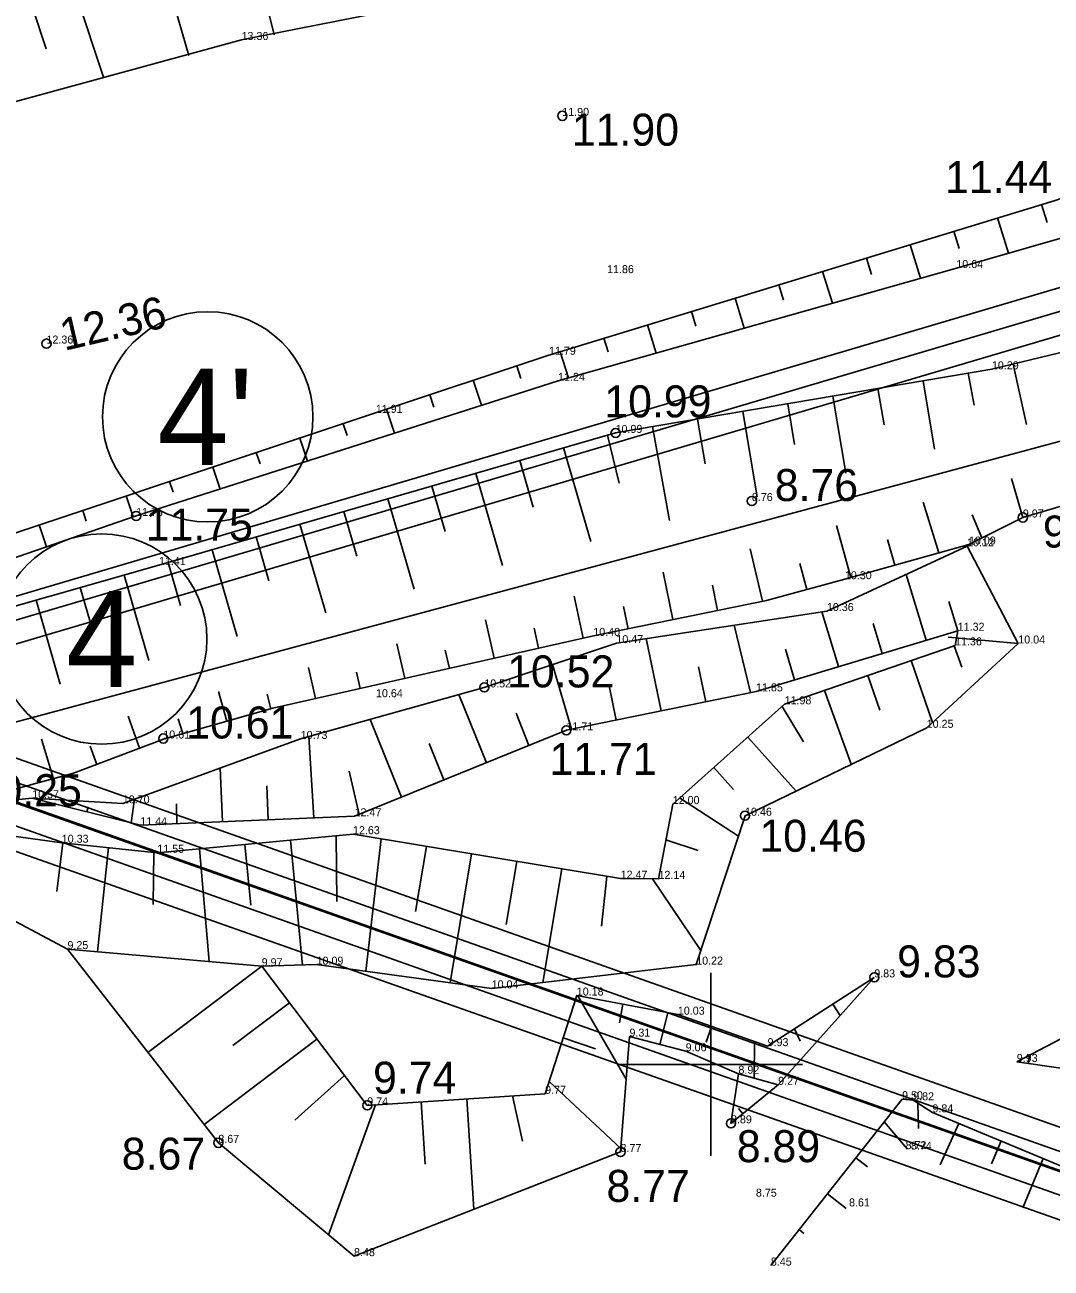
# Model space of a CAD drawing. Extents: x 433497 to 434382, y 6534486 to 6534993.
# Drawn here: x 433970 to 434014.9, y 6534891.1 to 6534945.5 of the extents above; entities that cross this region are included whole.
import ezdxf

# ---------------------------------------------------------------- set-up
doc = ezdxf.new("R2010")
doc.units = 0
for name, color, linetype in [('Default', 7, 'Continuous'), ('kataster', 7, 'Continuous'), ('KORGUS-EH2000', 7, 'Continuous'), ('MOOTKORG-EH2000', 7, 'Continuous'), ('PIIR', 7, 'Continuous'), ('RELJEEF', 7, 'Continuous'), ('VEEKOGU', 7, 'Continuous'), ('VORK', 7, 'Continuous')]:
    doc.layers.add(name, color=color, linetype=linetype)

msp = doc.modelspace()

# ---------------------------------------------------------------- linework, layer by layer
at = {"layer": 'Default'}
msp.add_lwpolyline([(433617.12, 6534791.025), (433632.75, 6534606.045), (434137.38, 6534796.515), (434127.69, 6534855.6), (433968.21, 6534911.925), (433942.38, 6534904.035), (433920.99, 6534907.275)], close=True, dxfattribs=at)
msp.add_lwpolyline([(433617.12, 6534791.025), (433632.75, 6534606.045), (434137.38, 6534796.515), (434127.69, 6534855.6), (433968.21, 6534911.925), (433942.38, 6534904.035), (433920.99, 6534907.275)], close=True, dxfattribs=at)
msp.add_lwpolyline([(433617.12, 6534791.025), (433632.75, 6534606.045), (434137.38, 6534796.515), (434127.69, 6534855.6), (433968.21, 6534911.925), (433942.38, 6534904.035), (433920.99, 6534907.275)], close=True, dxfattribs=at)
at = {"layer": 'kataster'}
msp.add_lwpolyline([(433617.102, 6534791.002), (433632.769, 6534606.029), (434137.446, 6534796.469), (434127.827, 6534855.589), (433950.026, 6534918.39)], close=True, dxfattribs=at)
at = {"layer": 'KORGUS-EH2000'}
for centre in [(433993.5, 6534941.49), (433970.95, 6534931.53), (433995.831, 6534927.622), (434001.79, 6534924.641), (433974.871, 6534923.99), (434013.638, 6534923.923), (433990.092, 6534916.489), (433976.058, 6534914.254), (433993.682, 6534914.612), (434001.493, 6534910.875), (434007.141, 6534903.804), (433984.974, 6534898.207), (434000.877, 6534897.42), (433978.465, 6534896.567), (433996.048, 6534896.167)]:
    msp.add_circle(centre, 0.2, dxfattribs=at)
at = {"layer": 'PIIR'}
for points in [[(433967.603, 6534912.278), (433955.91, 6534916.425), (434046.45, 6534943.215), (434054.366, 6534945.47)], [(433967.938, 6534913.221), (433959.144, 6534916.339), (434046.729, 6534942.255), (434054.64, 6534944.509)], [(433968.272, 6534914.163), (433962.378, 6534916.253), (434047.008, 6534941.294), (434054.914, 6534943.547)], [(434138.342, 6534801.592), (434129.36, 6534856.88), (433968.248, 6534913.871)], [(433632.021, 6534604.835), (434138.248, 6534795.936), (434128.468, 6534856.135), (433968.226, 6534912.818), (433942.33, 6534904.85), (433920.952, 6534908.165), (433616.327, 6534791.524), (433632.021, 6534604.835)], [(433632.732, 6534605.959), (434137.353, 6534796.454), (434127.754, 6534855.539), (433968.208, 6534911.976), (433942.39, 6534904.031), (433921.04, 6534907.341), (433617.174, 6534790.992), (433632.732, 6534605.959)]]:
    msp.add_lwpolyline(points, dxfattribs=at)
for points in [[(433618.234, 6534790.327), (433921.149, 6534906.313), (433942.464, 6534903.008), (433968.187, 6534910.923), (434126.862, 6534854.794), (434136.235, 6534797.101), (433633.617, 6534607.362)], [(433619.24, 6534789.695), (433634.52, 6534608.851), (434135.141, 6534797.808), (434125.908, 6534854.108), (433968.165, 6534909.82), (433942.53, 6534901.99), (433921.212, 6534905.219)], [(433619.24, 6534789.695), (433634.52, 6534608.851), (434135.141, 6534797.808), (434125.908, 6534854.108), (433968.165, 6534909.82), (433942.53, 6534901.99), (433921.212, 6534905.219)]]:
    msp.add_lwpolyline(points, close=True, dxfattribs=at)
for centre in [(433977.998, 6534928.325), (433973.364, 6534918.605)]:
    msp.add_circle(centre, 4.6, dxfattribs=at)
at = {"layer": 'RELJEEF'}
for p, q in [((433979.915, 6534949.055), (433980.899, 6534945.037)), ((433976.03, 6534948.103), (433977.167, 6534944.132)), ((433972.231, 6534946.852), (433973.457, 6534943.139)), ((433970.941, 6534944.427), (433970.332, 6534946.224)), ((434014.694, 6534936.827), (434014.446, 6534937.611)), ((434012.533, 6534937.026), (434013.004, 6534935.486)), ((434010.851, 6534935.687), (434010.621, 6534936.441)), ((434008.709, 6534935.855), (434009.158, 6534934.388)), ((434007.014, 6534934.556), (434006.796, 6534935.27)), ((434004.884, 6534934.685), (434005.308, 6534933.297)), ((434003.177, 6534933.426), (434002.971, 6534934.1)), ((434001.059, 6534933.515), (434001.459, 6534932.207)), ((433999.34, 6534932.295), (433999.146, 6534932.93)), ((433997.234, 6534932.344), (433997.609, 6534931.116)), ((433995.503, 6534931.165), (433995.321, 6534931.759)), ((433993.409, 6534931.174), (433993.77, 6534930.028)), ((433991.691, 6534929.996), (433991.507, 6534930.555)), ((434011.507, 6534928.837), (434011.248, 6534930.228)), ((434013.207, 6534930.626), (434013.794, 6534927.992)), ((433989.61, 6534929.922), (433989.974, 6534928.829)), ((434009.276, 6534929.894), (434009.78, 6534926.912)), ((433987.891, 6534928.754), (433987.712, 6534929.29)), ((434005.332, 6534929.228), (434005.9, 6534925.868)), ((434007.572, 6534927.976), (434007.304, 6534929.561)), ((433985.815, 6534928.658), (433986.165, 6534927.608)), ((434001.388, 6534928.561), (434002.02, 6534924.824)), ((434003.66, 6534927.12), (434003.36, 6534928.895)), ((433984.089, 6534927.512), (433983.918, 6534928.025)), ((433999.748, 6534926.265), (433999.416, 6534928.228)), ((433995.983, 6534925.428), (433995.481, 6534927.521)), ((433997.444, 6534927.895), (433998.182, 6534923.792)), ((433982.02, 6534927.393), (433982.355, 6534926.388)), ((433993.56, 6534926.964), (433994.747, 6534922.867)), ((433980.287, 6534926.269), (433980.123, 6534926.76)), ((433992.227, 6534924.378), (433991.639, 6534926.408)), ((433978.225, 6534926.128), (433978.546, 6534925.167)), ((433989.718, 6534925.852), (433990.883, 6534921.828)), ((433976.484, 6534925.026), (433976.328, 6534925.495)), ((433988.374, 6534923.302), (433987.797, 6534925.296)), ((434013.638, 6534923.923), (434013.134, 6534925.628)), ((433974.431, 6534924.863), (433974.737, 6534923.944)), ((433985.876, 6534924.739), (433987.02, 6534920.789)), ((433972.69, 6534923.761), (433972.533, 6534924.23)), ((433984.522, 6534922.226), (433983.955, 6534924.183)), ((434009.968, 6534922.374), (434009.273, 6534924.589)), ((433982.034, 6534923.627), (433983.157, 6534919.749)), ((434011.422, 6534924.04), (434011.85, 6534923.027)), ((433970.636, 6534923.598), (433970.955, 6534922.641)), ((434006.117, 6534921.292), (434005.488, 6534923.571)), ((433980.669, 6534921.15), (433980.113, 6534923.07)), ((434002.253, 6534920.26), (434001.715, 6534922.556)), ((434007.726, 6534922.96), (434008.042, 6534921.833)), ((433978.192, 6534922.514), (433979.293, 6534918.71)), ((433976.814, 6534920.073), (433976.271, 6534921.958)), ((433998.335, 6534919.455), (433997.908, 6534921.532)), ((434003.881, 6534921.913), (434004.186, 6534920.769)), ((433974.348, 6534921.406), (433975.419, 6534917.668)), ((434000.068, 6534920.955), (434000.294, 6534919.857)), ((434009.403, 6534918.551), (434008.536, 6534921.431)), ((433972.956, 6534919.002), (433972.425, 6534920.856)), ((433994.418, 6534918.641), (433994.017, 6534920.485)), ((433970.503, 6534920.306), (433971.555, 6534916.628)), ((433996.172, 6534920.031), (433996.376, 6534919.052)), ((434010.79, 6534918.968), (434010.407, 6534920.241)), ((433990.516, 6534917.761), (433990.137, 6534919.441)), ((434005.573, 6534917.398), (434004.85, 6534919.798)), ((434007.095, 6534919.279), (434007.488, 6534917.974)), ((433992.269, 6534919.081), (433992.467, 6534918.201)), ((434001.737, 6534916.266), (434001.01, 6534919.212)), ((434010.674, 6534918.326), (434010.79, 6534918.968)), ((433986.614, 6534916.881), (433986.272, 6534918.401)), ((433997.819, 6534915.462), (433997.169, 6534918.626)), ((434010.374, 6534918.689), (434013.438, 6534918.41)), ((434010.964, 6534917.373), (434010.639, 6534918.314)), ((433988.385, 6534918.121), (433988.565, 6534917.321)), ((434003.263, 6534918.158), (434003.658, 6534916.821)), ((434008.749, 6534917.661), (434009.684, 6534914.953)), ((433982.712, 6534916.001), (433982.404, 6534917.361)), ((433984.501, 6534917.161), (433984.663, 6534916.441)), ((433993.901, 6534914.657), (433993.074, 6534917.49)), ((433999.463, 6534917.396), (433999.778, 6534915.864)), ((433995.536, 6534916.634), (433995.86, 6534915.059)), ((434007.381, 6534915.495), (434006.858, 6534917.008)), ((433978.838, 6534915.012), (433978.473, 6534916.303)), ((433980.6, 6534916.194), (433980.762, 6534915.557)), ((433990.182, 6534913.192), (433988.972, 6534916.175)), ((434004.968, 6534916.355), (434006.137, 6534913.125)), ((434004.044, 6534914.107), (434003.108, 6534915.651)), ((433975.02, 6534913.83), (433974.515, 6534915.238)), ((433976.711, 6534915.121), (433976.914, 6534914.467)), ((433986.476, 6534911.687), (433985.096, 6534915.087)), ((433991.479, 6534915.356), (433992.036, 6534913.944)), ((433971.253, 6534912.495), (433970.736, 6534914.221)), ((433972.856, 6534913.916), (433973.15, 6534913.119)), ((433982.64, 6534910.778), (433982.426, 6534914.338)), ((433987.682, 6534914.035), (433988.329, 6534912.439)), ((434001.615, 6534914.319), (434003.724, 6534911.956)), ((433978.644, 6534910.611), (433978.546, 6534912.96)), ((433984.177, 6534912.82), (433984.623, 6534910.935)), ((434000.988, 6534912.018), (434000.123, 6534912.987)), ((433980.58, 6534912.185), (433980.642, 6534910.695)), ((433998.631, 6534911.656), (434001.199, 6534909.979)), ((433970.778, 6534911.527), (433970.788, 6534911.614)), ((433972.775, 6534911.271), (433972.719, 6534911.043)), ((433974.659, 6534910.559), (433974.795, 6534911.599)), ((433976.635, 6534911.395), (433976.646, 6534910.528)), ((433971.409, 6534907.556), (433971.666, 6534909.689)), ((433973.655, 6534909.48), (433973.178, 6534904.926)), ((433979.879, 6534906.966), (433979.627, 6534909.62)), ((433981.618, 6534909.809), (433982.137, 6534904.343)), ((433983.647, 6534907.117), (433983.609, 6534909.998)), ((433985.588, 6534909.863), (433984.911, 6534904.07)), ((433987.088, 6534906.687), (433987.561, 6534909.535)), ((433999.435, 6534909.348), (433998.033, 6534909.818)), ((433975.616, 6534906.993), (433975.645, 6534909.272)), ((433977.635, 6534909.431), (433978.067, 6534904.494)), ((433989.534, 6534909.207), (433988.597, 6534903.571)), ((433991.047, 6534906.112), (433991.507, 6534908.879)), ((433993.48, 6534908.551), (433992.654, 6534903.585)), ((433995.212, 6534906.039), (433995.453, 6534908.223)), ((433997.445, 6534908.115), (433999.556, 6534904.974)), ((433980.359, 6534904.292), (433975.387, 6534900.521)), ((434007.024, 6534903.703), (434007.013, 6534903.721)), ((434007.141, 6534903.804), (434007.141, 6534903.804)), ((433994.187, 6534903.001), (433996.294, 6534899.345)), ((433979.092, 6534900.821), (433981.568, 6534902.698)), ((433995.997, 6534901.814), (433996.152, 6534902.629)), ((434005.332, 6534902.637), (434005.653, 6534902.14)), ((433998.117, 6534902.257), (433997.768, 6534900.867)), ((433999.793, 6534900.973), (434000.021, 6534901.659)), ((434003.906, 6534901.013), (434003.651, 6534901.553)), ((433982.776, 6534901.105), (433977.844, 6534897.364)), ((433994.949, 6534900.682), (433993.539, 6534901.157)), ((434001.908, 6534900.996), (434001.885, 6534899.399)), ((434013.882, 6534900.032), (434013.934, 6534900.4)), ((434013.372, 6534900.105), (434013.372, 6534900.105)), ((433981.803, 6534897.557), (433983.985, 6534899.511)), ((433992.926, 6534899.253), (433996.06, 6534896.318)), ((433991.767, 6534896.643), (433991.324, 6534898.619)), ((434002.939, 6534899.105), (434000.877, 6534897.42)), ((433985.336, 6534898.231), (433983.28, 6534892.544)), ((433987.509, 6534895.629), (433987.332, 6534898.36)), ((433989.328, 6534898.49), (433989.641, 6534893.662)), ((434001.2, 6534898.072), (434001.39, 6534897.839)), ((434009.076, 6534897.191), (434009.05, 6534898.298)), ((434000.877, 6534897.42), (434000.877, 6534897.42)), ((434007.573, 6534897.482), (434008.59, 6534896.284)), ((434010.839, 6534897.418), (434010.018, 6534895.609)), ((434012.27, 6534895.652), (434012.685, 6534896.648)), ((434006.842, 6534895.512), (434006.335, 6534895.911)), ((434014.531, 6534895.879), (434013.635, 6534893.73)), ((434005.097, 6534894.341), (434005.918, 6534893.693)), ((434004.064, 6534892.608), (434003.859, 6534892.77)), ((434002.621, 6534891.199), (434002.621, 6534891.199))]:
    msp.add_line(p, q, dxfattribs=at)
for points in [[(433954.03, 6534938.79), (433965.22, 6534940.93), (433979.48, 6534944.81), (434000.61, 6534948.99), (434020.069, 6534953.305), (434024.103, 6534954.537)], [(433936.113, 6534913.569), (433948.309, 6534917.667), (433964.567, 6534921.575), (433985.421, 6534928.526), (433992.869, 6534931.009), (434015.046, 6534937.794), (434037.058, 6534945.242), (434046.777, 6534948.114)], [(434057.361, 6534943.115), (434035.636, 6534936.058), (434012.285, 6534930.403), (433995.831, 6534927.622), (433975.867, 6534921.841), (433966.352, 6534919.118), (433953.883, 6534915.376), (433941.75, 6534912.389)], [(434034.795, 6534941.742), (434010.729, 6534934.833), (433993.318, 6534929.9), (433974.871, 6534923.99), (433964.528, 6534920.427), (433953.287, 6534916.572), (433941.75, 6534912.389)], [(434013.638, 6534923.923), (434032.965, 6534929.639), (434058.719, 6534936.872), (434065.592, 6534938.633), (434071.86, 6534940.43)], [(434013.638, 6534923.923), (434011.282, 6534922.743), (434005.856, 6534921.218), (434002.425, 6534920.296), (433994.862, 6534918.741), (433980.849, 6534915.581), (433976.065, 6534914.227), (433972.133, 6534912.733), (433966.809, 6534911.293), (433961.061, 6534910.056), (433948.062, 6534907.022), (433934.725, 6534902.808)], [(434013.438, 6534918.41), (434011.201, 6534922.662), (434005.07, 6534919.831), (433995.866, 6534918.427), (433990.092, 6534916.489), (433982.062, 6534914.236), (433974.288, 6534911.415), (433970.327, 6534911.64)], [(433966.809, 6534911.293), (433970.327, 6534911.64), (433975.054, 6534910.461), (433984.421, 6534910.853), (433993.682, 6534914.612), (434001.975, 6534916.315), (434010.79, 6534918.968)], [(433934.885, 6534901.473), (433948.355, 6534905.609), (433960.823, 6534908.761), (433967.491, 6534910.261), (433971.618, 6534909.694), (433975.796, 6534909.256), (433984.352, 6534910.069), (433996.051, 6534908.124), (433997.709, 6534908.113), (433998.331, 6534911.388), (434003.22, 6534915.751), (434010.674, 6534918.326)], [(433935.534, 6534899.657), (433948.664, 6534904.432), (433960.648, 6534906.657), (433966.716, 6534907.784), (433971.868, 6534905.042), (433980.359, 6534904.292), (433982.759, 6534904.361), (433990.414, 6534903.325), (433999.356, 6534904.364), (434001.493, 6534910.875), (434009.433, 6534914.722), (434013.438, 6534918.41)], [(434072.341, 6534918.619), (434057.705, 6534915.179), (434049.799, 6534913.566), (434039.083, 6534902.565), (434026.545, 6534900.533), (434022.06, 6534899.903), (434019.453, 6534899.237), (434013.372, 6534900.105)], [(434013.372, 6534900.105), (434019.896, 6534903.523), (434025.539, 6534902.847), (434027.394, 6534902.614), (434034.232, 6534903.967), (434040.473, 6534912.406), (434048.11, 6534914.669), (434057.958, 6534916.499), (434064.857, 6534918.437), (434072.341, 6534918.619)], [(433971.868, 6534905.042), (433978.465, 6534896.567), (433984.397, 6534891.611), (433996.048, 6534896.167), (433996.438, 6534901.214), (433998.896, 6534900.572), (434001.203, 6534899.589), (434002.939, 6534899.105), (434007.141, 6534903.804)], [(433980.359, 6534904.292), (433984.974, 6534898.207), (433992.752, 6534898.712), (433994.135, 6534903.011), (433998.554, 6534902.174), (434002.477, 6534900.796), (434007.141, 6534903.804)], [(434000.877, 6534897.42), (434001.203, 6534899.589)], [(434002.621, 6534891.199), (434008.357, 6534898.477), (434008.844, 6534898.428), (434009.684, 6534897.899), (434020.673, 6534893.319), (434025.184, 6534891.367), (434026.4, 6534888.82), (434028.53, 6534881.31), (434029.71, 6534869.667), (434036.879, 6534848.772), (434040.385, 6534828.949), (434036.914, 6534815.456), (434039.48, 6534802.82), (434040.271, 6534794.377), (434046.22, 6534786.31), (434052.87, 6534782.4), (434066.43, 6534782.05), (434080.61, 6534786.771), (434096.029, 6534790.927), (434100.314, 6534792.082), (434103.079, 6534792.827), (434103.7, 6534784.75)]]:
    msp.add_lwpolyline(points, dxfattribs=at)
at = {"layer": 'VEEKOGU'}
msp.add_lwpolyline([(433938.353, 6534906.567), (434032.024, 6534931.768), (434057.768, 6534939.003)], dxfattribs=at)
at = {"layer": 'VORK'}
for p, q in [((434000, 6534904), (434000, 6534896)), ((433996, 6534900), (434004, 6534900))]:
    msp.add_line(p, q, dxfattribs=at)

# ---------------------------------------------------------------- texts
at = {"layer": 'KORGUS-EH2000'}
for s, p in [('11.90', (433993.92, 6534940.185)), ('11.44', (434010.236, 6534938.113)), ('10.99', (433995.339, 6534928.301)), ('8.76', (434002.79, 6534924.641)), ('11.75', (433975.291, 6534922.912)), ('9.97', (434014.514, 6534922.607)), ('10.52', (433991.092, 6534916.489)), ('10.61', (433977.058, 6534914.254)), ('11.71', (433992.941, 6534912.664)), ('10.25', (433967.809, 6534911.293)), ('10.46', (434002.12, 6534909.3)), ('9.83', (434008.141, 6534903.804)), ('9.74', (433985.228, 6534898.718)), ('8.89', (434001.131, 6534895.721)), ('8.67', (433974.243, 6534895.393)), ('8.77', (433995.432, 6534893.984))]:
    msp.add_text(s, height=1.4, dxfattribs=at).set_placement(p)
msp.add_text('12.36', height=1.4, rotation=13.1091, dxfattribs=at).set_placement((433971.732, 6534931.207))
at = {"layer": 'MOOTKORG-EH2000'}
for s, p in [('13.36', (433979.48, 6534944.81)), ('11.90', (433993.5, 6534941.49)), ('10.64', (434010.729, 6534934.833)), ('11.86', (433995.46, 6534934.61)), ('12.36', (433970.95, 6534931.53)), ('11.79', (433992.92, 6534931.04)), ('10.29', (434012.285, 6534930.403)), ('11.24', (433993.318, 6534929.9)), ('11.91', (433985.35, 6534928.5)), ('10.99', (433995.831, 6534927.622)), ('8.76', (434001.79, 6534924.641)), ('11.75', (433974.871, 6534923.99)), ('9.97', (434013.638, 6534923.923)), ('10.09', (434011.281, 6534922.739)), ('10.12', (434011.201, 6534922.662)), ('11.41', (433975.867, 6534921.841)), ('10.30', (434005.857, 6534921.221)), ('10.36', (434005.07, 6534919.831)), ('11.32', (434010.79, 6534918.968)), ('10.40', (433994.857, 6534918.742)), ('10.47', (433995.866, 6534918.427)), ('10.04', (434013.438, 6534918.41)), ('11.36', (434010.674, 6534918.326)), ('10.52', (433990.092, 6534916.489)), ('11.85', (434001.975, 6534916.315)), ('10.64', (433985.356, 6534916.06)), ('11.98', (434003.22, 6534915.751)), ('11.71', (433993.682, 6534914.612)), ('10.25', (434009.433, 6534914.722)), ('10.61', (433976.058, 6534914.254)), ('10.73', (433982.062, 6534914.236)), ('10.57', (433970.327, 6534911.64)), ('10.70', (433974.288, 6534911.415)), ('12.00', (433998.331, 6534911.388)), ('12.47', (433984.421, 6534910.853)), ('10.46', (434001.493, 6534910.875)), ('11.44', (433975.054, 6534910.461)), ('10.33', (433971.618, 6534909.694)), ('12.63', (433984.352, 6534910.069)), ('11.55', (433975.796, 6534909.256)), ('12.47', (433996.051, 6534908.124)), ('12.14', (433997.709, 6534908.113)), ('9.25', (433971.868, 6534905.042)), ('9.97', (433980.359, 6534904.292)), ('10.09', (433982.759, 6534904.361)), ('10.22', (433999.356, 6534904.364)), ('9.83', (434007.141, 6534903.804)), ('10.04', (433990.414, 6534903.325)), ('10.18', (433994.135, 6534903.011)), ('10.03', (433998.554, 6534902.174)), ('9.31', (433996.438, 6534901.214)), ('9.06', (433998.896, 6534900.572)), ('9.93', (434002.477, 6534900.796)), ('9.93', (434013.372, 6534900.105)), ('8.92', (434001.203, 6534899.589)), ('9.27', (434002.939, 6534899.105)), ('9.77', (433992.752, 6534898.712)), ('9.50', (434008.357, 6534898.477)), ('9.82', (434008.844, 6534898.428)), ('9.74', (433984.974, 6534898.207)), ('9.84', (434009.684, 6534897.899)), ('8.89', (434000.877, 6534897.42)), ('8.67', (433978.465, 6534896.567)), ('8.77', (433996.048, 6534896.167)), ('8.72', (434008.512, 6534896.291)), ('8.74', (434008.744, 6534896.27)), ('8.75', (434001.967, 6534894.211)), ('8.61', (434006.038, 6534893.784)), ('8.48', (433984.397, 6534891.611)), ('8.45', (434002.621, 6534891.199))]:
    msp.add_text(s, height=0.35, dxfattribs=at).set_placement(p)
at = {"layer": 'PIIR'}
for s, p in [("4'", (433975.797, 6534926.225)), ('4', (433971.8, 6534916.505))]:
    msp.add_text(s, height=4.2, dxfattribs=at).set_placement(p)

doc.saveas('drawing.dxf')
